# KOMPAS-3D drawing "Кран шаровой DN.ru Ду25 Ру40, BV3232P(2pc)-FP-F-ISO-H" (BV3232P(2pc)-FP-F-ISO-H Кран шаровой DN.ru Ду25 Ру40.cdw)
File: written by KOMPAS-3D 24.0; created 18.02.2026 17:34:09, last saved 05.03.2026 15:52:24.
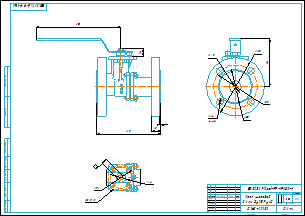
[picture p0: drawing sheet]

Document properties: Автор: R2D2; Форматы листов документа: A2; Полное имя файла: BV3232P(2pc)-FP-F-ISO-H Кран шаровой DN.ru Ду25 Ру40.m3d; Масса: 3.68; Наименование: Кран шаровой DN.ru Ду25 Ру40; Количество листов документа: 1; Примечание: D160-22131

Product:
- Part/product: Кран шаровой DN.ru Ду25 Ру40  | designation BV3232P(2pc)-FP-F-ISO-H
    Масса: 3.68
    Раздел спецификации: Прочие изделия
    Форматы листов документа: A2
    Примечание: D160-22131

Views: Проекционный вид 2, Проекционный вид 3
Referenced files in E:\Работа\Зайцев\BV3232P(2pc)-FP-F-ISO-H Кран шаровой DN.ru Ду15-300 Ру16-40\DN25\: BV3232P(2pc)-FP-F-ISO-H Кран шаровой DN.ru Ду25 Ру40.m3d
Referenced files in E:\Работа\Зайцев\Для компаса\: чертеж DN.ru А3.cdt
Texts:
  BV3232P(2pc)-FP-F-ISO-H
  ISO 5211
  чертеж DN.ru А3.cdt
  Кран шаровой
  DN.ru Ду25 Ру40
  Кран шаровой DN.ru Ду25 Ру40
  BV3232P(2pc)-FP-F-ISO-H Кран шаровой DN.ru Ду25 Ру40
Dimensions and other numbers on the sheet: 0; 3; 4; 94; 115; 85; 68; 25; 14; 4 отв.; 11; 50; 42; 1:1; 1; 2; 3,68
